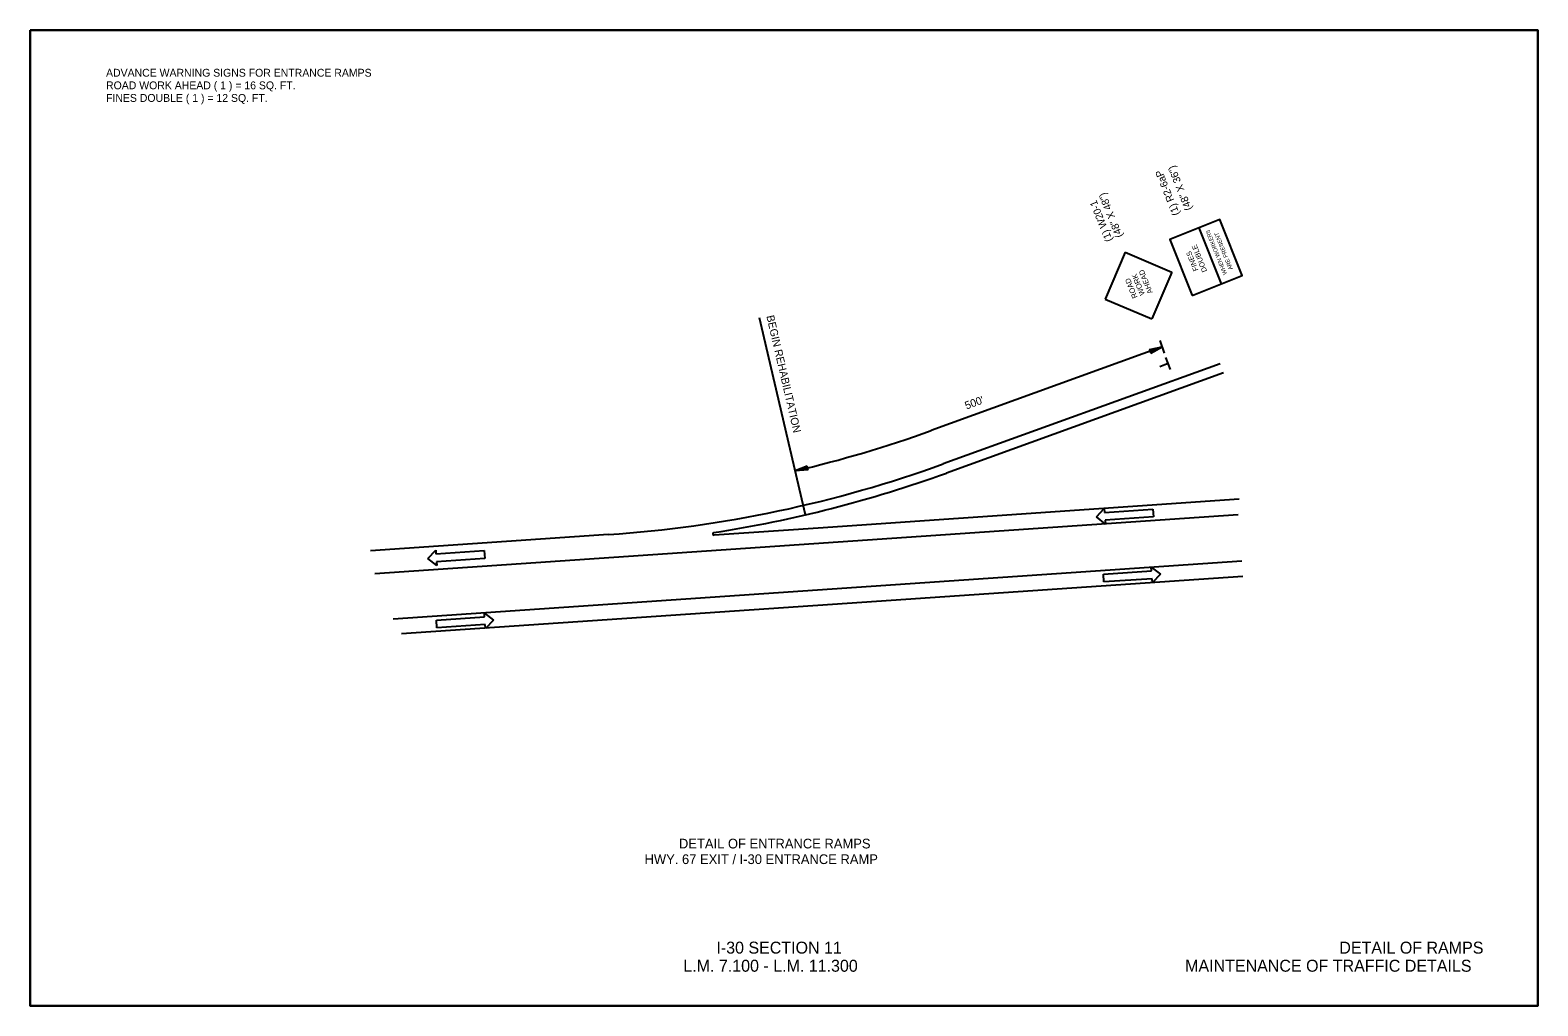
# Model space of a CAD drawing. Extents: x 1374027 to 1374537, y 380415 to 381405.
# Drawn here: x 1374027.1 to 1374197.1, y 381075.2 to 381185.2 of the extents above; entities that cross this region are included whole.
import ezdxf

# ---------------------------------------------------------------- set-up
doc = ezdxf.new("R2010")
doc.units = 0
for name, color, linetype in [('Default', 7, 'Continuous'), ('DSN_DRFT_Junk-No-Plot', 7, 'Continuous'), ('R_Border Notes', 7, 'Continuous'), ('R_Draft', 7, 'Continuous'), ('R_Exist Surface', 7, 'Continuous'), ('R_MOT', 7, 'Continuous')]:
    doc.layers.add(name, color=color, linetype=linetype)

msp = doc.modelspace()

# ---------------------------------------------------------------- linework, layer by layer
at = {"layer": 'DSN_DRFT_Junk-No-Plot'}
for points in [[(1374027.08, 381185.17), (1374197.08, 381185.17), (1374197.08, 381075.17), (1374027.08, 381075.17)], [(1374027.08, 381185.17), (1374027.08, 381075.17), (1374197.08, 381075.17), (1374197.08, 381185.17)]]:
    msp.add_lwpolyline(points, close=True, dxfattribs=at)
at = {"layer": 'R_Draft'}
for p, q in [((1374153.29, 381149.17), (1374154.73, 381149.46)), ((1374153.29, 381149.17), (1374153.44, 381148.76)), ((1374153.3, 381149.14), (1374154.51, 381149.38)), ((1374153.32, 381149.1), (1374154.27, 381149.3)), ((1374153.33, 381149.07), (1374154.04, 381149.21)), ((1374153.34, 381149.03), (1374153.81, 381149.13)), ((1374153.35, 381149), (1374153.58, 381149.05)), ((1374153.38, 381148.94), (1374153.58, 381149.05)), ((1374153.39, 381148.9), (1374153.81, 381149.13)), ((1374153.4, 381148.87), (1374154.04, 381149.21)), ((1374153.41, 381148.83), (1374154.27, 381149.3)), ((1374153.43, 381148.8), (1374154.51, 381149.38)), ((1374153.44, 381148.76), (1374154.73, 381149.46)), ((1374114.7, 381136.03), (1374113.33, 381135.48)), ((1374114.8, 381135.61), (1374113.33, 381135.48)), ((1374114.71, 381136), (1374113.57, 381135.54)), ((1374114.79, 381135.64), (1374113.57, 381135.54)), ((1374114.72, 381135.96), (1374113.81, 381135.6)), ((1374114.78, 381135.68), (1374113.81, 381135.6)), ((1374114.72, 381135.93), (1374114.05, 381135.65)), ((1374114.77, 381135.72), (1374114.05, 381135.65)), ((1374114.73, 381135.89), (1374114.29, 381135.71)), ((1374114.77, 381135.75), (1374114.29, 381135.71)), ((1374114.74, 381135.86), (1374114.53, 381135.77)), ((1374114.76, 381135.79), (1374114.53, 381135.77)), ((1374114.8, 381135.61), (1374114.7, 381136.03))]:
    msp.add_line(p, q, dxfattribs=at)
at = {"layer": 'R_Exist Surface'}
for p, q in [((1374161.26, 381147.57), (1374130.03, 381136.27)), ((1374161.63, 381146.54), (1374130.4, 381135.24)), ((1374163.42, 381132.28), (1374115.95, 381129.04)), ((1374163.3, 381130.52), (1374065.96, 381123.88)), ((1374092.28, 381128.31), (1374065.45, 381126.48)), ((1374115.95, 381129.04), (1374104.2, 381128.24)), ((1374163.69, 381125.32), (1374068, 381118.78)), ((1374163.83, 381123.58), (1374119.2, 381120.53)), ((1374119.2, 381120.53), (1374068.95, 381117.11))]:
    msp.add_line(p, q, dxfattribs=at)
for centre, radius, start, end in [((1374082.85, 381266.59), 138.6, 273.9033, 289.9033), ((1374082.85, 381266.59), 139.69, 278.7808, 289.9033), ((1374104.19, 381128.39), 0.146, 98.7808, 273.9002)]:
    msp.add_arc(centre, radius, start, end, dxfattribs=at)
at = {"layer": 'R_MOT'}
for p, q in [((1374158.85, 381162.87), (1374161.39, 381156.56)), ((1374150.54, 381160.14), (1374148.29, 381154.86)), ((1374150.54, 381160.14), (1374155.82, 381157.89)), ((1374155.82, 381157.89), (1374153.57, 381152.61)), ((1374148.29, 381154.86), (1374153.57, 381152.61)), ((1374114.49, 381130.52), (1374109.32, 381152.75)), ((1374154.73, 381149.46), (1374128.67, 381140.03)), ((1374154.99, 381148.76), (1374154.48, 381150.17)), ((1374155.4, 381147.59), (1374154.46, 381147.23)), ((1374155.66, 381146.92), (1374155.14, 381148.27)), ((1374147.31, 381130.3), (1374148.2, 381131.24)), ((1374148.32, 381129.49), (1374147.31, 381130.3)), ((1374148.2, 381131.24), (1374148.23, 381130.8)), ((1374148.23, 381130.8), (1374153.68, 381131.17)), ((1374153.74, 381130.3), (1374148.29, 381129.93)), ((1374148.29, 381129.93), (1374148.32, 381129.49)), ((1374153.68, 381131.17), (1374153.74, 381130.3)), ((1374071.91, 381125.62), (1374072.81, 381126.56)), ((1374072.81, 381126.56), (1374072.84, 381126.12)), ((1374072.84, 381126.12), (1374078.28, 381126.5)), ((1374078.28, 381126.5), (1374078.34, 381125.62)), ((1374072.93, 381124.82), (1374071.91, 381125.62)), ((1374078.34, 381125.62), (1374072.9, 381125.25)), ((1374072.9, 381125.25), (1374072.93, 381124.82)), ((1374148.09, 381123.83), (1374153.53, 381124.2)), ((1374148.14, 381122.96), (1374148.09, 381123.83)), ((1374153.59, 381123.33), (1374148.14, 381122.96)), ((1374153.53, 381124.2), (1374153.5, 381124.64)), ((1374153.5, 381124.64), (1374154.52, 381123.83)), ((1374153.62, 381122.89), (1374153.59, 381123.33)), ((1374154.52, 381123.83), (1374153.62, 381122.89)), ((1374072.89, 381118.65), (1374078.33, 381119.02)), ((1374072.95, 381117.78), (1374072.89, 381118.65)), ((1374078.39, 381118.15), (1374072.95, 381117.78)), ((1374078.33, 381119.02), (1374078.3, 381119.46)), ((1374078.3, 381119.46), (1374079.32, 381118.65)), ((1374078.42, 381117.71), (1374078.39, 381118.15)), ((1374079.32, 381118.65), (1374078.42, 381117.71))]:
    msp.add_line(p, q, dxfattribs=at)
msp.add_lwpolyline([(1374158.12, 381155.24), (1374163.76, 381157.52), (1374161.22, 381163.83), (1374155.58, 381161.56)], close=True, dxfattribs=at)
msp.add_arc((1374082.85, 381266.59), 134.6, 283.09, 289.9033, dxfattribs=at)

# ---------------------------------------------------------------- texts
at = {"layer": 'Default'}
for s, p in [('DETAIL OF ENTRANCE RAMPS', (1374100.24, 381092.92)), ('HWY. 67 EXIT / I-30 ENTRANCE RAMP', (1374096.36, 381091.16))]:
    msp.add_text(s, height=1.0929, dxfattribs=at).set_placement(p)
at = {"layer": 'R_Border Notes'}
for s, p in [('I-30 SECTION 11', (1374104.46, 381081.06)), ('DETAIL OF RAMPS', (1374174.7, 381081.06)), ('L.M. 7.100 - L.M. 11.300', (1374100.73, 381079.02)), ('MAINTENANCE OF TRAFFIC DETAILS', (1374157.31, 381079.02))]:
    msp.add_text(s, height=1.35, dxfattribs=at).set_placement(p)
at = {"layer": 'R_MOT'}
for s, p in [('ADVANCE WARNING SIGNS FOR ENTRANCE RAMPS', (1374035.64, 381179.93)), ('ROAD WORK AHEAD ( 1 ) = 16 SQ. FT.', (1374035.64, 381178.51)), ('FINES DOUBLE ( 1 ) = 12 SQ. FT.', (1374035.64, 381177.09))]:
    msp.add_text(s, height=0.8838, dxfattribs=at).set_placement(p)
for s, height, rotation, p in [('(1) R2-6aP', 0.83, 111.9298, (1374156.71, 381164.46)), ('(48" X 36")', 0.83, 111.9298, (1374158.11, 381165.03)), ('(1) W20-1', 0.831, 111.9287, (1374149.14, 381161.5)), ('(48" X 48")', 0.8306, 111.9287, (1374150.3, 381161.97)), ('WHEN WORKERS', 0.4619, 111.9298, (1374162.05, 381157.7)), ('ARE PRESENT', 0.4619, 111.9298, (1374162.7, 381158.25)), ('DOUBLE', 0.577, 111.9298, (1374159.8, 381158.02)), ('FINES', 0.577, 111.9298, (1374158.82, 381158.14)), ('ROAD', 0.598, 111.9291, (1374151.96, 381155.07)), ('WORK', 0.598, 111.9287, (1374152.79, 381155.4)), ('AHEAD', 0.598, 111.9292, (1374153.68, 381155.6)), ('BEGIN REHABILITATION', 0.8743, 283.0886, (1374110.09, 381152.93)), ("500'", 0.874, 19.9044, (1374132.66, 381142.4))]:
    msp.add_text(s, height=height, rotation=rotation, dxfattribs=at).set_placement(p)

doc.saveas('drawing.dxf')
